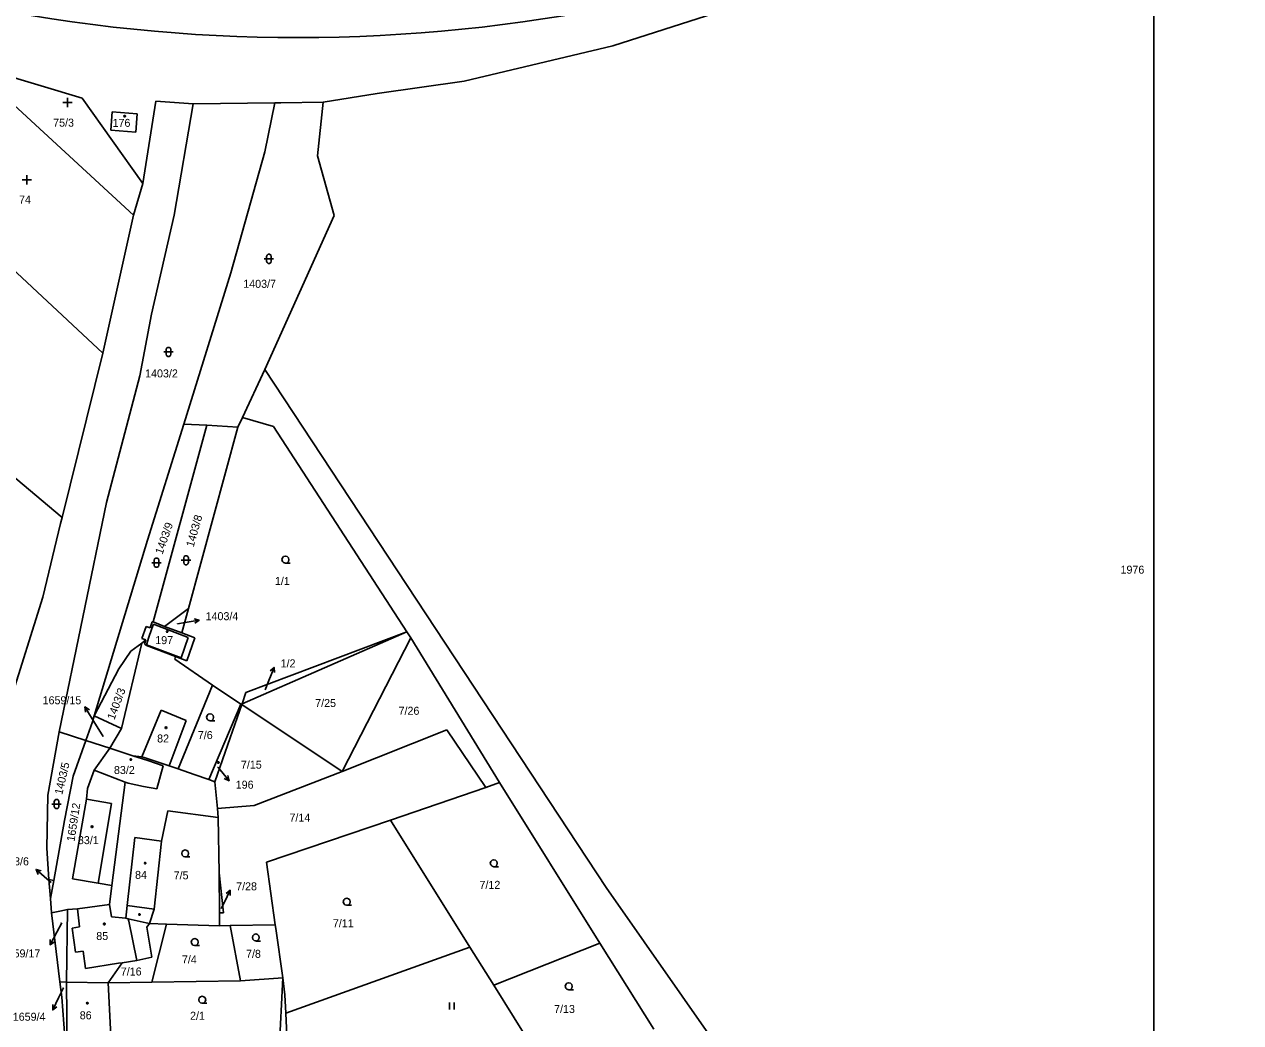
# Model space of a CAD drawing. Extents: x -802857 to -799647, y -1020285 to -1015884.
# Drawn here: x -801490 to -801231.6, y -1017461.1 to -1017248.9 of the extents above; entities that cross this region are included whole.
import ezdxf

# ---------------------------------------------------------------- set-up
doc = ezdxf.new("R2010")
doc.units = 0
for name, color, linetype in [('Default', 7, 'Continuous'), ('KLADY_ZMVM', 7, 'Continuous'), ('KN_HRANICE', 7, 'Continuous'), ('KN_KULTURY', 7, 'Continuous'), ('KN_PARCELY', 7, 'Continuous'), ('KN_SLUCKY', 7, 'Continuous'), ('Železniční svršek', 7, 'Continuous')]:
    doc.layers.add(name, color=color, linetype=linetype)

# ---------------------------------------------------------------- blocks, each defined once
blk = doc.blocks.new('304')
at = {"layer": 'Default'}
blk.add_lwpolyline([(0, 0), (-0.38, 0.1), (-0.65, 0.37), (-0.75, 0.74), (-0.65, 1.11), (-0.38, 1.38), (-0.01, 1.48), (0.36, 1.38), (0.63, 1.11), (0.73, 0.73), (0.63, 0.35), (0.36, 0.08), (-0.02, -0.02), (0.98, -0.02)], dxfattribs=at)
blk = doc.blocks.new('306')
at = {"layer": 'Default'}
for p, q in [((-0.5, 1.5), (-0.5, 0)), ((0.5, 0), (0.5, 1.5))]:
    blk.add_line(p, q, dxfattribs=at)
blk = doc.blocks.new('315')
at = {"layer": 'Default'}
for p, q in [((-1, 1), (1, 1)), ((0, 0), (0, 2))]:
    blk.add_line(p, q, dxfattribs=at)
blk = doc.blocks.new('316')
at = {"layer": 'Default'}
for points in [[(-1, 1), (0.27, 1), (1, 1)], [(-0.5, 1.5), (-0.4, 1.79), (-0.15, 1.97), (0.16, 1.97), (0.41, 1.79), (0.51, 1.5), (0.51, 0.5), (0.41, 0.21), (0.16, 0.03), (-0.15, 0.03), (-0.4, 0.21), (-0.5, 0.5), (-0.5, 1.5)]]:
    blk.add_lwpolyline(points, dxfattribs=at)
blk = doc.blocks.new('NAHRADNI_SYMBOL')
at = {"layer": 'Default'}
blk.add_lwpolyline([(0.09, 0.15), (0.18, 0), (0.09, -0.15), (-0.09, -0.15), (-0.18, 0), (-0.09, 0.15), (0.09, 0.15)], dxfattribs=at)
blk = doc.blocks.new('10292')
at = {"layer": 'Default'}
blk.add_line((0, 3), (0, 0), dxfattribs=at)
blk.add_lwpolyline([(-0.5, 2), (0, 3), (0.5, 2)], dxfattribs=at)
blk = doc.blocks.new('402')
at = {"layer": 'Default'}
blk.add_lwpolyline([(0.09, 0.15), (0.18, 0), (0.09, -0.15), (-0.09, -0.15), (-0.18, 0), (-0.09, 0.15), (0.09, 0.15)], dxfattribs=at)

msp = doc.modelspace()

# ---------------------------------------------------------------- linework, layer by layer
at = {"layer": 'KLADY_ZMVM'}
msp.add_lwpolyline([(-801250, -1017000), (-801250, -1017500), (-801250, -1018000)], dxfattribs=at)
at = {"layer": 'KN_HRANICE'}
for p, q in [((-801619.51, -1017238.39), (-801481.95, -1017353.71)), ((-801318.92, -1017238.69), (-801364.93, -1017253.53)), ((-801364.93, -1017253.53), (-801396.54, -1017260.97)), ((-801477.73, -1017264.63), (-801501.56, -1017257.45)), ((-801466.82, -1017289.45), (-801501.56, -1017257.45)), ((-801396.54, -1017260.97), (-801415.01, -1017263.64)), ((-801415.01, -1017263.64), (-801426.49, -1017265.49)), ((-801477.73, -1017264.63), (-801464.79, -1017282.78)), ((-801464.79, -1017282.78), (-801462.07, -1017265.26)), ((-801454.13, -1017265.82), (-801462.07, -1017265.26)), ((-801454.13, -1017265.82), (-801458.15, -1017289.48)), ((-801454.13, -1017265.82), (-801436.73, -1017265.61)), ((-801438.87, -1017276.02), (-801436.73, -1017265.61)), ((-801436.73, -1017265.61), (-801435.52, -1017265.6)), ((-801435.52, -1017265.6), (-801426.49, -1017265.49)), ((-801426.49, -1017265.49), (-801427.72, -1017276.85)), ((-801471.6, -1017271.43), (-801471.3, -1017267.55)), ((-801471.3, -1017267.55), (-801466, -1017267.95)), ((-801466, -1017267.95), (-801466.29, -1017271.83)), ((-801466.29, -1017271.83), (-801471.6, -1017271.43)), ((-801473.28, -1017318.78), (-801518.94, -1017276.33)), ((-801446.14, -1017301.75), (-801438.87, -1017276.02)), ((-801427.72, -1017276.85), (-801424.14, -1017289.58)), ((-801466.82, -1017289.45), (-801464.79, -1017282.78)), ((-801473.28, -1017318.78), (-801466.82, -1017289.45)), ((-801458.15, -1017289.48), (-801462.97, -1017310.53)), ((-801424.14, -1017289.58), (-801438.92, -1017322.27)), ((-801456.12, -1017333.87), (-801446.14, -1017301.75)), ((-801462.97, -1017310.53), (-801465.45, -1017323.65)), ((-801481.95, -1017353.71), (-801473.28, -1017318.78)), ((-801465.45, -1017323.65), (-801472.56, -1017350.57)), ((-801443.65, -1017332.48), (-801438.92, -1017322.27)), ((-801438.92, -1017322.27), (-801366.39, -1017432.38)), ((-801463.78, -1017358.51), (-801456.12, -1017333.87)), ((-801451.19, -1017334.14), (-801462.64, -1017375.93)), ((-801451.19, -1017334.14), (-801456.12, -1017333.87)), ((-801444.59, -1017334.5), (-801451.19, -1017334.14)), ((-801444.59, -1017334.5), (-801443.65, -1017332.48)), ((-801443.65, -1017332.48), (-801437.03, -1017334.42)), ((-801455.08, -1017373.05), (-801444.59, -1017334.5)), ((-801437.03, -1017334.42), (-801408.69, -1017378.05)), ((-801472.56, -1017350.57), (-801482.61, -1017399.26)), ((-801486.04, -1017370.69), (-801482.28, -1017355.03)), ((-801482.28, -1017355.03), (-801481.95, -1017353.71)), ((-801475.12, -1017395.87), (-801463.78, -1017358.51)), ((-801493.03, -1017393.07), (-801486.04, -1017370.69)), ((-801460.21, -1017376.86), (-801455.08, -1017373.05)), ((-801456.5, -1017378.26), (-801455.08, -1017373.05)), ((-801464.99, -1017379.43), (-801464.11, -1017376.89)), ((-801464.11, -1017376.89), (-801463.26, -1017377.18)), ((-801463.26, -1017377.18), (-801462.81, -1017375.87)), ((-801462.81, -1017375.87), (-801462.64, -1017375.93)), ((-801462.64, -1017375.93), (-801460.21, -1017376.86)), ((-801460.21, -1017376.86), (-801456.5, -1017378.26)), ((-801453.76, -1017379.27), (-801456.5, -1017378.26)), ((-801443.73, -1017393.29), (-801408.69, -1017378.05)), ((-801442.91, -1017390.9), (-801408.69, -1017378.05)), ((-801407.88, -1017379.29), (-801408.69, -1017378.05)), ((-801469.37, -1017398.55), (-801465.04, -1017380.4)), ((-801465.04, -1017380.4), (-801467.33, -1017382.12)), ((-801464.14, -1017379.72), (-801465.04, -1017380.4)), ((-801464.14, -1017379.72), (-801464.99, -1017379.43)), ((-801464.45, -1017380.63), (-801464.14, -1017379.72)), ((-801464.01, -1017380.93), (-801464.45, -1017380.63)), ((-801453.76, -1017379.27), (-801455.47, -1017384.17)), ((-801422.42, -1017407.74), (-801407.88, -1017379.29)), ((-801407.88, -1017379.29), (-801389.06, -1017410.03)), ((-801469.88, -1017385.9), (-801467.33, -1017382.12)), ((-801457.88, -1017383.3), (-801464.01, -1017380.93)), ((-801457.88, -1017383.3), (-801458, -1017383.82)), ((-801455.47, -1017384.17), (-801457.88, -1017383.3)), ((-801475.12, -1017395.87), (-801469.88, -1017385.9)), ((-801450.03, -1017389.33), (-801458, -1017383.82)), ((-801450.03, -1017389.33), (-801457.32, -1017407.16)), ((-801443.97, -1017393.39), (-801450.03, -1017389.33)), ((-801443.73, -1017393.29), (-801442.91, -1017390.9)), ((-801443.97, -1017393.39), (-801450.79, -1017409.43)), ((-801446.23, -1017400.56), (-801443.8, -1017393.5)), ((-801443.97, -1017393.39), (-801443.73, -1017393.29)), ((-801443.8, -1017393.5), (-801443.73, -1017393.29)), ((-801443.8, -1017393.5), (-801422.42, -1017407.74)), ((-801475.51, -1017397.16), (-801475.12, -1017395.87)), ((-801469.37, -1017398.55), (-801475.12, -1017395.87)), ((-801476.91, -1017401.11), (-801475.51, -1017397.16)), ((-801471.82, -1017402.77), (-801469.37, -1017398.55)), ((-801400.24, -1017398.84), (-801422.42, -1017407.74)), ((-801391.91, -1017411.13), (-801400.24, -1017398.84)), ((-801484.97, -1017412.74), (-801482.61, -1017399.26)), ((-801476.91, -1017401.11), (-801482.61, -1017399.26)), ((-801479.6, -1017408.7), (-801476.91, -1017401.11)), ((-801471.82, -1017402.77), (-801476.91, -1017401.11)), ((-801449.49, -1017409.89), (-801446.23, -1017400.56)), ((-801475.18, -1017407.42), (-801471.82, -1017402.77)), ((-801471.82, -1017402.77), (-801466.9, -1017404.38)), ((-801466.9, -1017404.38), (-801463.71, -1017405.36)), ((-801466.9, -1017404.38), (-801464.99, -1017404.58)), ((-801464.3, -1017404.78), (-801464.99, -1017404.58)), ((-801459.24, -1017406.5), (-801464.3, -1017404.78)), ((-801463.71, -1017405.36), (-801460.5, -1017406.5)), ((-801460.5, -1017406.5), (-801461.81, -1017411.42)), ((-801457.32, -1017407.16), (-801459.24, -1017406.5)), ((-801481.43, -1017418.11), (-801479.6, -1017408.7)), ((-801475.18, -1017407.42), (-801476.57, -1017411.34)), ((-801468.57, -1017409.95), (-801475.18, -1017407.42)), ((-801453.89, -1017408.33), (-801457.32, -1017407.16)), ((-801450.79, -1017409.43), (-801453.89, -1017408.33)), ((-801422.42, -1017407.74), (-801441.13, -1017414.93)), ((-801476.57, -1017411.34), (-801476.78, -1017413.57)), ((-801468.57, -1017409.95), (-801471.37, -1017431.95)), ((-801467.94, -1017410.19), (-801468.57, -1017409.95)), ((-801464.69, -1017410.9), (-801467.94, -1017410.19)), ((-801461.81, -1017411.42), (-801464.69, -1017410.9)), ((-801449.49, -1017409.89), (-801450.79, -1017409.43)), ((-801449.49, -1017409.89), (-801448.95, -1017415.59)), ((-801412.18, -1017418.02), (-801391.91, -1017411.13)), ((-801391.91, -1017411.13), (-801389.06, -1017410.03)), ((-801367.72, -1017444.15), (-801389.06, -1017410.03)), ((-801485.18, -1017423.98), (-801484.97, -1017412.74)), ((-801476.78, -1017413.57), (-801479.73, -1017430.52)), ((-801459.51, -1017416.03), (-801460.82, -1017422.5)), ((-801448.78, -1017417.45), (-801459.51, -1017416.03)), ((-801441.13, -1017414.93), (-801448.95, -1017415.59)), ((-801448.95, -1017415.59), (-801448.78, -1017417.45)), ((-801483.75, -1017430.88), (-801481.43, -1017418.11)), ((-801448.78, -1017417.45), (-801448.56, -1017429.24)), ((-801438.55, -1017426.97), (-801412.18, -1017418.02)), ((-801395.3, -1017445.02), (-801412.18, -1017418.02)), ((-801484.77, -1017430.63), (-801485.18, -1017423.98)), ((-801460.82, -1017422.5), (-801462.42, -1017436.96)), ((-801438.55, -1017426.97), (-801436.67, -1017440.26)), ((-801448.56, -1017429.24), (-801447.64, -1017437.77)), ((-801448.56, -1017429.24), (-801448.55, -1017437.77)), ((-801484.44, -1017434.71), (-801484.77, -1017430.63)), ((-801484.77, -1017430.63), (-801483.75, -1017430.88)), ((-801484.44, -1017434.71), (-801483.75, -1017430.88)), ((-801479.73, -1017430.52), (-801474.31, -1017431.46)), ((-801474.31, -1017431.46), (-801471.37, -1017431.95)), ((-801471.37, -1017431.95), (-801471.88, -1017435.96)), ((-801366.39, -1017432.38), (-801324.28, -1017492.5)), ((-801484.2, -1017437.73), (-801484.44, -1017434.71)), ((-801482.44, -1017437.37), (-801484.2, -1017437.73)), ((-801484.2, -1017437.73), (-801482.44, -1017452.42)), ((-801480.79, -1017437.04), (-801482.44, -1017437.37)), ((-801481.05, -1017452.5), (-801480.79, -1017437.04)), ((-801480.79, -1017437.04), (-801478.66, -1017436.87)), ((-801478.66, -1017436.87), (-801471.88, -1017435.96)), ((-801471.88, -1017435.96), (-801471.48, -1017438.57)), ((-801462.42, -1017436.96), (-801463.38, -1017440.03)), ((-801471.48, -1017438.57), (-801468.43, -1017438.86)), ((-801467.91, -1017438.98), (-801468.43, -1017438.86)), ((-801464.08, -1017439.87), (-801467.91, -1017438.98)), ((-801463.38, -1017440.03), (-801464.08, -1017439.87)), ((-801463.93, -1017440.81), (-801463.38, -1017440.03)), ((-801463.38, -1017440.03), (-801459.78, -1017440.14)), ((-801462.91, -1017452.5), (-801459.78, -1017440.14)), ((-801459.78, -1017440.14), (-801448.54, -1017440.47)), ((-801447.64, -1017437.77), (-801448.55, -1017437.77)), ((-801448.55, -1017437.77), (-801448.54, -1017440.47)), ((-801436.67, -1017440.26), (-801446.24, -1017440.43)), ((-801436.67, -1017440.26), (-801436.56, -1017441.04)), ((-801462.92, -1017447.17), (-801463.93, -1017440.81)), ((-801446.24, -1017440.43), (-801448.54, -1017440.47)), ((-801446.24, -1017440.43), (-801444.06, -1017452.22)), ((-801436.56, -1017441.04), (-801435.08, -1017451.54)), ((-801395.3, -1017445.02), (-801434.42, -1017459.09)), ((-801390.25, -1017453.11), (-801395.3, -1017445.02)), ((-801367.72, -1017444.15), (-801390.25, -1017453.11)), ((-801356.25, -1017462.47), (-801367.72, -1017444.15)), ((-801469.2, -1017448.34), (-801466.08, -1017447.84)), ((-801466.08, -1017447.84), (-801462.92, -1017447.17)), ((-801469.2, -1017448.34), (-801472.2, -1017452.64)), ((-801482.44, -1017452.42), (-801481.05, -1017452.5)), ((-801482.44, -1017452.42), (-801481.99, -1017455.66)), ((-801472.2, -1017452.64), (-801481.05, -1017452.5)), ((-801481.05, -1017452.5), (-801480.85, -1017471.15)), ((-801462.91, -1017452.5), (-801472.2, -1017452.64)), ((-801472.2, -1017452.64), (-801471.55, -1017465.31)), ((-801444.06, -1017452.22), (-801462.91, -1017452.5)), ((-801435.08, -1017451.54), (-801444.06, -1017452.22)), ((-801435.08, -1017451.54), (-801436.26, -1017476.56)), ((-801435.08, -1017451.54), (-801434.61, -1017455.17)), ((-801379.24, -1017470.71), (-801390.25, -1017453.11)), ((-801480.85, -1017471.15), (-801481.99, -1017455.66)), ((-801434.61, -1017455.17), (-801434.42, -1017459.09)), ((-801434.42, -1017459.09), (-801433.35, -1017480.9))]:
    msp.add_line(p, q, dxfattribs=at)
at = {"layer": 'KN_PARCELY'}
for p, q in [((-801457.41, -1017376.35), (-801455.81, -1017376.07)), ((-801438.84, -1017390.35), (-801438.04, -1017388.36)), ((-801473.22, -1017400.28), (-801475.54, -1017396.53)), ((-801448.9, -1017406.77), (-801448.4, -1017407.37)), ((-801484.27, -1017431.32), (-801485.23, -1017430.49)), ((-801448.16, -1017436.83), (-801447.56, -1017435.64)), ((-801482.04, -1017439.87), (-801483.1, -1017441.87)), ((-801481.69, -1017453.66), (-801482.65, -1017455.66))]:
    msp.add_line(p, q, dxfattribs=at)
at = {"layer": 'KN_SLUCKY'}
for p, q in [((-801463.58, -1017379.36), (-801462.86, -1017377.32)), ((-801462.86, -1017377.32), (-801462.55, -1017376.41)), ((-801462.55, -1017376.41), (-801455.19, -1017379.23)), ((-801464.05, -1017380.77), (-801463.74, -1017379.86)), ((-801456.68, -1017383.56), (-801464.05, -1017380.77)), ((-801463.74, -1017379.86), (-801463.58, -1017379.36)), ((-801455.19, -1017379.23), (-801456.68, -1017383.56)), ((-801464.99, -1017404.58), (-801460.92, -1017394.66)), ((-801460.92, -1017394.66), (-801455.63, -1017396.89)), ((-801455.63, -1017396.89), (-801459.24, -1017406.5)), ((-801471.46, -1017414.5), (-801476.78, -1017413.57)), ((-801474.31, -1017431.46), (-801471.46, -1017414.5)), ((-801466.53, -1017421.73), (-801468.13, -1017436.19)), ((-801460.82, -1017422.5), (-801466.53, -1017421.73)), ((-801478.66, -1017436.87), (-801478.26, -1017440.73)), ((-801468.13, -1017436.19), (-801468.43, -1017438.86)), ((-801462.42, -1017436.96), (-801468.13, -1017436.19)), ((-801467.91, -1017438.98), (-801467.8, -1017439.52)), ((-801467.8, -1017439.52), (-801466.08, -1017447.84)), ((-801478.26, -1017440.73), (-801479.84, -1017440.98)), ((-801479.84, -1017440.98), (-801479.1, -1017446.07)), ((-801479.1, -1017446.07), (-801477.5, -1017445.91)), ((-801477.5, -1017445.91), (-801476.98, -1017449.6)), ((-801476.98, -1017449.6), (-801469.95, -1017448.47)), ((-801469.95, -1017448.47), (-801469.2, -1017448.34))]:
    msp.add_line(p, q, dxfattribs=at)
at = {"layer": 'Železniční svršek'}
msp.add_arc((-801431.93, -1016905.94), 345.8, 259.1164, 305.4132, dxfattribs=at)

# ---------------------------------------------------------------- block references
at = {"layer": 'KN_KULTURY'}
for name, p in [('315', (-801480.81, -1017266.56)), ('402', (-801468.66, -1017268.45)), ('315', (-801489.43, -1017282.97)), ('316', (-801438.02, -1017299.77)), ('316', (-801459.36, -1017319.54)), ('316', (-801461.92, -1017364.33)), ('316', (-801455.63, -1017363.81)), ('304', (-801434.51, -1017363.42)), ('402', (-801459.63, -1017377.97)), ('304', (-801450.51, -1017396.92)), ('402', (-801459.9, -1017398.39)), ('402', (-801467.35, -1017405.18)), ('NAHRADNI_SYMBOL', (-801448.77, -1017405.79)), ('316', (-801483.13, -1017415.62)), ('402', (-801475.59, -1017419.42)), ('304', (-801455.8, -1017425.84)), ('402', (-801464.3, -1017427.17)), ('304', (-801390.23, -1017427.94)), ('304', (-801421.48, -1017436.11)), ('402', (-801472.99, -1017440.12)), ('402', (-801465.5, -1017438.1)), ('304', (-801440.79, -1017443.71)), ('304', (-801453.78, -1017444.69)), ('304', (-801374.31, -1017454.09)), ('304', (-801452.18, -1017456.94)), ('NAHRADNI_SYMBOL', (-801476.59, -1017456.92)), ('306', (-801399.14, -1017458.26))]:
    msp.add_blockref(name, p, dxfattribs=at)
at = {"layer": 'KN_PARCELY'}
for p, rotation in [((-801455.81, -1017376.07), -80.05282100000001), ((-801438.04, -1017388.36), -21.897605), ((-801475.54, -1017396.53), 31.741862), ((-801448.4, -1017407.37), -139.81231900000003), ((-801485.23, -1017430.49), 49.15977900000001), ((-801447.56, -1017435.64), -26.595858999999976), ((-801483.1, -1017441.87), 152.005703), ((-801482.65, -1017455.66), 154.469422)]:
    msp.add_blockref('10292', p, dxfattribs=dict(at, rotation=rotation))

# ---------------------------------------------------------------- texts
for s, height, p in [('75/3', 1.7, (-801483.86, -1017270.67)), ('176', 1.7, (-801471.24, -1017270.72)), ('74', 1.7, (-801491.11, -1017287.01)), ('1403/7', 1.7, (-801443.47, -1017304.92)), ('1403/2', 1.7, (-801464.32, -1017323.96)), ('1976', 1.7, (-801257.08, -1017365.67)), ('1/1', 1.7, (-801436.75, -1017368.08)), ('1403/4', 1.7, (-801451.47, -1017375.55)), ('1403/4', 0.1, (-801457.71, -1017376.35)), ('197', 1.7, (-801462.17, -1017380.64)), ('1/2', 1.7, (-801435.53, -1017385.58)), ('1/2', 0.1, (-801438.99, -1017390.35)), ('1659/15', 1.7, (-801486.1, -1017393.42)), ('7/25', 1.7, (-801428.19, -1017394)), ('7/26', 1.7, (-801410.47, -1017395.65)), ('1659/15', 0.1, (-801473.57, -1017400.28)), ('82', 1.7, (-801461.77, -1017401.54)), ('7/6', 1.7, (-801453.12, -1017400.81)), ('83/2', 1.7, (-801470.94, -1017408.24)), ('196', 0.1, (-801449.05, -1017406.77)), ('7/15', 1.7, (-801443.97, -1017407.1)), ('196', 1.7, (-801445.07, -1017411.36)), ('7/14', 1.7, (-801433.65, -1017418.35)), ('83/1', 1.7, (-801478.6, -1017423.14)), ('1403/6', 1.7, (-801495.96, -1017427.64)), ('84', 1.7, (-801466.46, -1017430.53)), ('7/5', 1.7, (-801458.26, -1017430.62)), ('1403/6', 0.1, (-801484.57, -1017431.32)), ('7/28', 1.7, (-801444.98, -1017432.96)), ('7/12', 1.7, (-801393.28, -1017432.64)), ('7/28', 0.1, (-801448.36, -1017436.83)), ('1659/17', 0.1, (-801482.39, -1017439.87)), ('7/11', 1.7, (-801424.43, -1017440.81)), ('85', 1.7, (-801474.7, -1017443.51)), ('1659/17', 1.7, (-801494.8, -1017447.21)), ('7/4', 1.7, (-801456.5, -1017448.5)), ('7/8', 1.7, (-801442.88, -1017447.3)), ('7/16', 1.7, (-801469.49, -1017451.06)), ('1659/4', 0.1, (-801481.99, -1017453.66)), ('7/13', 1.7, (-801377.43, -1017459.02)), ('1659/4', 1.7, (-801492.44, -1017460.67)), ('86', 1.7, (-801478.21, -1017460.36)), ('2/1', 1.7, (-801454.77, -1017460.46))]:
    msp.add_text(s, height=height, dxfattribs=at).set_placement(p)
for s, rotation, p in [('1403/9', 70.703, (-801460.64, -1017361.7)), ('1403/8', 74.141, (-801454.03, -1017360.14)), ('1403/3', 69.614, (-801470.86, -1017396.86)), ('1403/5', 76.834, (-801481.93, -1017412.74)), ('1659/12', 81.245, (-801479.33, -1017422.67))]:
    msp.add_text(s, height=1.7, rotation=rotation, dxfattribs=at).set_placement(p)

doc.saveas('drawing.dxf')
